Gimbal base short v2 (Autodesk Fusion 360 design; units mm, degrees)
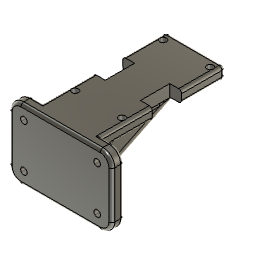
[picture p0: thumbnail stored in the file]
sketch "草图1" plane through (0, 0, 0) normal (0, 0, 1) x axis (1, 0, 0)
  line L1 (0, -25) -> (0, 9)
  line L2 (-10, -4.75) -> (-6, -4.75)
  line L3 (-10, 9) -> (-10, -25)
  line L4 (-10, 9) -> (10, -25)
  line L5 (-6, -14.75) -> (-10, -14.75)
  line L6 (10, -9.75) -> (-10, -9.75)
  line L7 (10, -4.75) -> (6, -4.75)
  line L8 (-10, -25) -> (10, -25)
  line L9 (10, -25) -> (10, 9)
  line L10 (10, 9) -> (-10, 9)
  line L11 (10, 9) -> (-10, -25)
  line L12 (-6, -4.75) -> (-10, -14.75)
  line L13 (10, -14.75) -> (10, -4.75)
  line L14 (-10, -4.75) -> (-6, -14.75)
  line L15 (6, -14.75) -> (10, -14.75)
  line L16 (-6, -4.75) -> (-6, -14.75)
  line L17 (6, -4.75) -> (6, -14.75)
  line L18 (10, -8) -> (-10, -8)
  line L19 (-10, -14.75) -> (-10, -4.75)
  line L20 (10, -25) -> (-10, -25)
  line L21 (10, -36) -> (10, -25)
  line L22 (-10, -36) -> (10, -36)
  line L23 (-10, -25) -> (-10, -36)
  circle C1 centre (0, 0) radius 1.3
  circle C2 centre (0, 0) radius 3
  circle C3 centre (8, -23) radius 1.125
  circle C4 centre (0, 0) radius 4
  circle C5 centre (8, 7) radius 1.125
  circle C6 centre (-8, 7) radius 1.125
  circle C7 centre (-8, -23) radius 1.125
  point P26 (0, -8)
  point P21 (0, -8)
  point P8 (-8, -9.75)
  point P4 (-10, -14.75)
  point P19 (0, 9)
  point P20 (0, -25)
  point P10 (10, -14.75)
  point P5 (-6, -14.75)
  point P12 (6, -14.75)
  point P6 (-6, -4.75)
  point P11 (6, -4.75)
  point P7 (-10, -4.75)
  point P9 (10, -4.75)
  point P3 (10, -9.75)
  point P2 (-10, -9.75)
  point P13 (0, 0)
  point P15 (-10, -8)
  point P29 (10, -8)
  point P1 (0, 0)
  point P27 (0, 0)
  point P24 (-10, 9)
  point P25 (10, 9)
  point P22 (10, -25)
  point P14 (-8, 7)
  horizontal L8
  perpendicular L3 L8
  parallel L8 L10
  parallel L3 L9
  coincident P26 L4
  coincident P26 L11
  coincident P21 P26
  horizontal L5
  perpendicular L5 L16
  parallel L2 L5
  parallel L16 L19
  coincident P8 L12
  coincident P8 L14
  coincident P4 L3
  coincident P8 L6
  midpoint P19 L10
  midpoint P20 L8
  symmetric P4 P10 L1
  symmetric P5 P12 L1
  symmetric P6 P11 L1
  symmetric P7 P9 L1
  midpoint P3 L13
  midpoint P2 L19
  coincident P13 L1
  midpoint P15 L3
  midpoint P29 L9
  symmetric L1 C5 C6
  symmetric C6 C7 L18
  symmetric C3 C5 L18
  concentric C1 C2
  concentric C2 C4
  horizontal L20
  vertical L21
  horizontal L22
  vertical L23
  collinear L9 L21
  coincident P1 P27
  dimension "d1" distance P24 P25 = 20
  dimension "d2" distance P22 P25 = 34
  dimension "d3" distance P5 P6 = 10
  dimension "d4" distance P6 P7 = 4
  dimension "d5" diameter C1 = 2.6
  dimension "d6" distance P14 L1 = 8
  dimension "d7" distance P14 L18 = 15
  dimension "d8" diameter C6 = 2.25
  dimension "d9" distance P13 P14 = 7
  dimension "d10" diameter C2 = 6
  dimension "d11" diameter C4 = 8
  dimension "d12" distance L8 L15 = 10.25
  dimension "d13" distance L10 L22 = 45
extrude "拉伸1" new body sketch "草图1" profile of C1 L2 L3 L5 L7 C3 L8 L9 L10 C5 C6 L15 C7 L16 L17 L20 L21 L22 L23 along normal blind 4
sketch "草图2" plane through (0, -36, 0) normal (0, -1, 0) x axis (1, 0, 0)
  line L1 (10, 0) -> (-10, 0)
  line L2 (10, 4) -> (10, 0)
  line L3 (-10, 4) -> (10, 4)
  line L4 (-10, 0) -> (-10, 4)
  line L5 (0, -8.0576) -> (0, 4)
  line L6 (17.5, -20) -> (-17.5, -20)
  line L7 (17.5, 4) -> (17.5, -20)
  line L8 (-17.5, 4) -> (17.5, 4)
  line L9 (-17.5, -20) -> (-17.5, 4)
  line L10 (17.5, -8) -> (-17.5, -8)
  line L11 (0, -20.1153) -> (0, 4)
  line L12 (-12.5, -0.5) -> (12.5, -0.5)
  circle C1 centre (12.5, -0.5) radius 1.125
  circle C2 centre (-12.5, -0.5) radius 1.125
  circle C3 centre (12.5, -15.5) radius 1.125
  circle C4 centre (-12.5, -15.5) radius 1.125
  point P6 (0, 4)
  point P7 (0, -8.0576)
  point P8 (0, -8.0576)
  point P14 (0, 4)
  point P9 (0, -20.1153)
  point P15 (0, -20.1153)
  point P16 (-17.5, -8)
  point P17 (17.5, -8)
  point P18 (12.5, -0.5)
  point P22 (12.5, -0.5)
  point P20 (-12.5, -0.5)
  point P23 (-12.5, -0.5)
  point P19 (12.5, -15.5)
  point P10 (-17.5, -20)
  point P13 (-17.5, 4)
  point P11 (17.5, -20)
  midpoint L3 P6
  perpendicular L3 L5
  coincident P7 P8
  midpoint P14 L8
  coincident P9 P15
  midpoint P16 L9
  midpoint P17 L7
  symmetric C1 C3 L10
  symmetric C1 C2 L11
  symmetric C3 C4 L11
  vertical L9
  vertical L7
  horizontal L8
  collinear L3 L8
  midpoint P8 L11
  perpendicular L6 L9
  coincident P18 P22
  coincident P20 P23
  parallel L6 L12
  dimension "d16" distance P18 P19 = 15
  dimension "d17" distance P18 P20 = 25
  dimension "d18" distance P10 P13 = 24
  dimension "d19" distance P10 P11 = 35
  dimension "d20" diameter C2 = 2.25
extrude "拉伸2" add sketch "草图2" profile of L1 L2 L4 L6 L7 L8 L9 C1 C2 C3 C4 against normal blind 4
sketch "草图3" plane through (0, 0, 0) normal (1, 0, 0) x axis (0, 1, 0)
extrude "拉伸3" add sketch "草图3" distance 4
fillet "圆角3" radius 4
fillet "圆角4" radius 4
fillet "圆角5" radius 1
fillet "圆角6" radius 1
extrude "拉伸4" add of existing geometry blind 1
fillet "圆角7" radius 1
fillet "圆角8" radius 4
fillet "圆角9" radius 3
fillet "圆角10" radius 1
